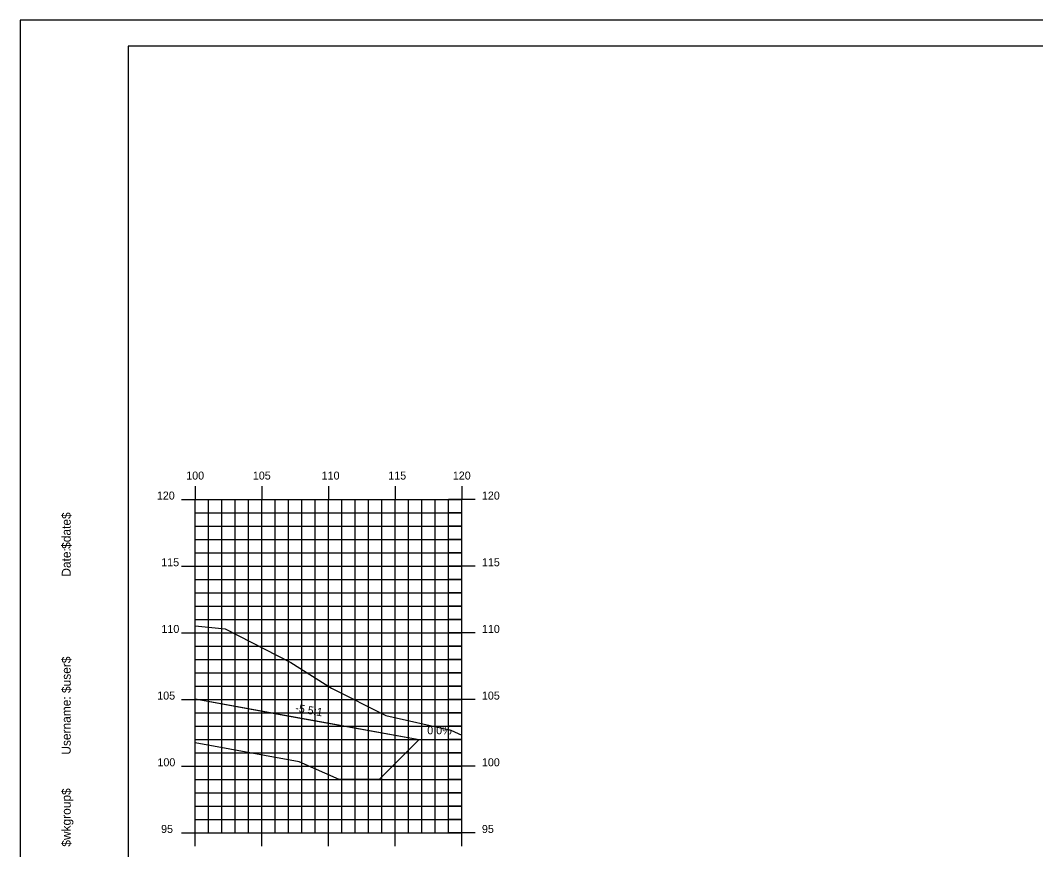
# Model space of a CAD drawing. Extents: x 850598 to 870284, y 366541 to 366651.
# Drawn here: x 858137.5 to 858213.6, y 366589 to 366651.2 of the extents above; entities that cross this region are included whole.
import ezdxf

# ---------------------------------------------------------------- set-up
doc = ezdxf.new("R2010")
doc.units = 0
for name, color, linetype in [('ANNOTATION', 7, 'Continuous'), ('BORDER', 7, 'Continuous'), ('D_Drainage_RipRap', 7, 'Continuous'), ('D_Roadway_Centerline', 7, 'Continuous'), ('D_Roadway_SlopeLines', 7, 'Continuous'), ('H_V ANNOTATION', 7, 'Continuous'), ('MAJOR', 7, 'Continuous'), ('MINOR', 7, 'Continuous'), ('PLOT BOUNDARY', 7, 'Continuous'), ('S_Roadway_Centerline', 7, 'Continuous')]:
    doc.layers.add(name, color=color, linetype=linetype)

msp = doc.modelspace()

# ---------------------------------------------------------------- linework, layer by layer
at = {"layer": 'BORDER'}
for p, q in [((858305.62, 366649.225), (858145.62, 366649.225)), ((858145.62, 366649.225), (858145.62, 366544.225))]:
    msp.add_line(p, q, dxfattribs=at)
at = {"layer": 'D_Drainage_RipRap'}
msp.add_lwpolyline([(858150.619, 366596.978), (858150.619, 366600.272), (858157.555, 366599.014), (858167.417, 366597.225), (858164.417, 366594.225), (858161.417, 366594.225), (858158.417, 366595.564)], close=True, dxfattribs=at)
at = {"layer": 'D_Roadway_Centerline'}
msp.add_lwpolyline([(858150.619, 366600.272), (858157.555, 366599.014), (858167.417, 366597.225), (858170.619, 366597.225)], dxfattribs=at)
at = {"layer": 'D_Roadway_SlopeLines'}
msp.add_lwpolyline([(858150.619, 366600.272), (858167.417, 366597.225)], dxfattribs=at)
at = {"layer": 'MAJOR'}
for p, q in [((858150.619, 366616.227), (858150.619, 366615.225)), ((858150.619, 366616.227), (858150.619, 366615.225)), ((858155.619, 366616.227), (858155.619, 366615.225)), ((858155.619, 366616.227), (858155.619, 366615.225)), ((858160.619, 366616.227), (858160.619, 366615.225)), ((858160.619, 366616.227), (858160.619, 366615.225)), ((858165.619, 366616.227), (858165.619, 366615.225)), ((858165.619, 366616.227), (858165.619, 366615.225)), ((858170.619, 366616.227), (858170.619, 366615.225)), ((858170.619, 366616.227), (858170.619, 366615.225)), ((858149.617, 366615.225), (858150.619, 366615.225)), ((858149.617, 366615.225), (858150.619, 366615.225)), ((858150.619, 366615.225), (858170.619, 366615.225)), ((858150.619, 366590.225), (858150.619, 366615.225)), ((858150.619, 366590.225), (858150.619, 366615.225)), ((858150.619, 366615.225), (858170.619, 366615.225)), ((858150.619, 366615.225), (858170.619, 366615.225)), ((858150.619, 366590.225), (858150.619, 366615.225)), ((858150.619, 366590.225), (858150.619, 366615.225)), ((858150.619, 366615.225), (858170.619, 366615.225)), ((858155.619, 366590.225), (858155.619, 366615.225)), ((858155.619, 366590.225), (858155.619, 366615.225)), ((858160.619, 366590.225), (858160.619, 366615.225)), ((858160.619, 366590.225), (858160.619, 366615.225)), ((858165.619, 366590.225), (858165.619, 366615.225)), ((858165.619, 366590.225), (858165.619, 366615.225)), ((858171.621, 366615.225), (858169.617, 366615.225)), ((858171.621, 366615.225), (858169.617, 366615.225)), ((858170.619, 366590.225), (858170.619, 366615.225)), ((858170.619, 366590.225), (858170.619, 366615.225)), ((858170.619, 366590.225), (858170.619, 366615.225)), ((858170.619, 366590.225), (858170.619, 366615.225)), ((858149.617, 366610.225), (858150.619, 366610.225)), ((858149.617, 366610.225), (858150.619, 366610.225)), ((858150.619, 366610.225), (858170.619, 366610.225)), ((858150.619, 366610.225), (858170.619, 366610.225)), ((858171.621, 366610.225), (858169.617, 366610.225)), ((858171.621, 366610.225), (858169.617, 366610.225)), ((858149.617, 366605.225), (858150.619, 366605.225)), ((858149.617, 366605.225), (858150.619, 366605.225)), ((858150.619, 366605.225), (858170.619, 366605.225)), ((858150.619, 366605.225), (858170.619, 366605.225)), ((858171.621, 366605.225), (858169.617, 366605.225)), ((858171.621, 366605.225), (858169.617, 366605.225)), ((858149.617, 366600.225), (858150.619, 366600.225)), ((858149.617, 366600.225), (858150.619, 366600.225)), ((858150.619, 366600.225), (858170.619, 366600.225)), ((858150.619, 366600.225), (858170.619, 366600.225)), ((858171.621, 366600.225), (858169.617, 366600.225)), ((858171.621, 366600.225), (858169.617, 366600.225)), ((858149.617, 366595.225), (858150.619, 366595.225)), ((858149.617, 366595.225), (858150.619, 366595.225)), ((858150.619, 366595.225), (858170.619, 366595.225)), ((858150.619, 366595.225), (858170.619, 366595.225)), ((858171.621, 366595.225), (858169.617, 366595.225)), ((858171.621, 366595.225), (858169.617, 366595.225)), ((858149.617, 366590.225), (858150.619, 366590.225)), ((858149.617, 366590.225), (858150.619, 366590.225)), ((858150.619, 366590.225), (858170.619, 366590.225)), ((858150.619, 366590.225), (858170.619, 366590.225)), ((858150.619, 366589.223), (858150.619, 366590.225)), ((858150.619, 366590.225), (858170.619, 366590.225)), ((858150.619, 366590.225), (858170.619, 366590.225)), ((858150.619, 366589.223), (858150.619, 366590.225)), ((858155.619, 366589.223), (858155.619, 366590.225)), ((858155.619, 366589.223), (858155.619, 366590.225)), ((858160.619, 366589.223), (858160.619, 366590.225)), ((858160.619, 366589.223), (858160.619, 366590.225)), ((858165.619, 366589.223), (858165.619, 366590.225)), ((858165.619, 366589.223), (858165.619, 366590.225)), ((858171.621, 366590.225), (858169.617, 366590.225)), ((858171.621, 366590.225), (858169.617, 366590.225)), ((858170.619, 366589.223), (858170.619, 366590.225)), ((858170.619, 366589.223), (858170.619, 366590.225))]:
    msp.add_line(p, q, dxfattribs=at)
at = {"layer": 'MINOR'}
for p, q in [((858151.619, 366590.225), (858151.619, 366615.225)), ((858151.619, 366590.225), (858151.619, 366615.225)), ((858152.619, 366590.225), (858152.619, 366615.225)), ((858152.619, 366590.225), (858152.619, 366615.225)), ((858153.619, 366590.225), (858153.619, 366615.225)), ((858153.619, 366590.225), (858153.619, 366615.225)), ((858154.619, 366590.225), (858154.619, 366615.225)), ((858154.619, 366590.225), (858154.619, 366615.225)), ((858156.619, 366590.225), (858156.619, 366615.225)), ((858156.619, 366590.225), (858156.619, 366615.225)), ((858157.619, 366590.225), (858157.619, 366615.225)), ((858157.619, 366590.225), (858157.619, 366615.225)), ((858158.619, 366590.225), (858158.619, 366615.225)), ((858158.619, 366590.225), (858158.619, 366615.225)), ((858159.619, 366590.225), (858159.619, 366615.225)), ((858159.619, 366590.225), (858159.619, 366615.225)), ((858161.619, 366590.225), (858161.619, 366615.225)), ((858161.619, 366590.225), (858161.619, 366615.225)), ((858162.619, 366590.225), (858162.619, 366615.225)), ((858162.619, 366590.225), (858162.619, 366615.225)), ((858163.619, 366590.225), (858163.619, 366615.225)), ((858163.619, 366590.225), (858163.619, 366615.225)), ((858164.619, 366590.225), (858164.619, 366615.225)), ((858164.619, 366590.225), (858164.619, 366615.225)), ((858166.619, 366590.225), (858166.619, 366615.225)), ((858166.619, 366590.225), (858166.619, 366615.225)), ((858167.619, 366590.225), (858167.619, 366615.225)), ((858167.619, 366590.225), (858167.619, 366615.225)), ((858168.619, 366590.225), (858168.619, 366615.225)), ((858168.619, 366590.225), (858168.619, 366615.225)), ((858169.619, 366590.225), (858169.619, 366615.225)), ((858169.619, 366590.225), (858169.619, 366615.225)), ((858150.619, 366614.225), (858170.619, 366614.225)), ((858150.619, 366614.225), (858151.621, 366614.225)), ((858150.619, 366614.225), (858170.619, 366614.225)), ((858150.619, 366614.225), (858151.621, 366614.225)), ((858170.619, 366614.225), (858169.617, 366614.225)), ((858170.619, 366614.225), (858169.617, 366614.225)), ((858150.619, 366613.225), (858170.619, 366613.225)), ((858150.619, 366613.225), (858151.621, 366613.225)), ((858150.619, 366613.225), (858170.619, 366613.225)), ((858150.619, 366613.225), (858151.621, 366613.225)), ((858170.619, 366613.225), (858169.617, 366613.225)), ((858170.619, 366613.225), (858169.617, 366613.225)), ((858150.619, 366612.225), (858170.619, 366612.225)), ((858150.619, 366612.225), (858151.621, 366612.225)), ((858150.619, 366612.225), (858170.619, 366612.225)), ((858150.619, 366612.225), (858151.621, 366612.225)), ((858170.619, 366612.225), (858169.617, 366612.225)), ((858170.619, 366612.225), (858169.617, 366612.225)), ((858150.619, 366611.225), (858170.619, 366611.225)), ((858150.619, 366611.225), (858151.621, 366611.225)), ((858150.619, 366611.225), (858170.619, 366611.225)), ((858150.619, 366611.225), (858151.621, 366611.225)), ((858170.619, 366611.225), (858169.617, 366611.225)), ((858170.619, 366611.225), (858169.617, 366611.225)), ((858150.619, 366609.225), (858170.619, 366609.225)), ((858150.619, 366609.225), (858151.621, 366609.225)), ((858150.619, 366609.225), (858170.619, 366609.225)), ((858150.619, 366609.225), (858151.621, 366609.225)), ((858170.619, 366609.225), (858169.617, 366609.225)), ((858170.619, 366609.225), (858169.617, 366609.225)), ((858150.619, 366608.225), (858170.619, 366608.225)), ((858150.619, 366608.225), (858151.621, 366608.225)), ((858150.619, 366608.225), (858170.619, 366608.225)), ((858150.619, 366608.225), (858151.621, 366608.225)), ((858170.619, 366608.225), (858169.617, 366608.225)), ((858170.619, 366608.225), (858169.617, 366608.225)), ((858150.619, 366607.225), (858170.619, 366607.225)), ((858150.619, 366607.225), (858151.621, 366607.225)), ((858150.619, 366607.225), (858170.619, 366607.225)), ((858150.619, 366607.225), (858151.621, 366607.225)), ((858170.619, 366607.225), (858169.617, 366607.225)), ((858170.619, 366607.225), (858169.617, 366607.225)), ((858150.619, 366606.225), (858170.619, 366606.225)), ((858150.619, 366606.225), (858151.621, 366606.225)), ((858150.619, 366606.225), (858170.619, 366606.225)), ((858150.619, 366606.225), (858151.621, 366606.225)), ((858170.619, 366606.225), (858169.617, 366606.225)), ((858170.619, 366606.225), (858169.617, 366606.225)), ((858150.619, 366604.225), (858170.619, 366604.225)), ((858150.619, 366604.225), (858151.621, 366604.225)), ((858150.619, 366604.225), (858170.619, 366604.225)), ((858150.619, 366604.225), (858151.621, 366604.225)), ((858170.619, 366604.225), (858169.617, 366604.225)), ((858170.619, 366604.225), (858169.617, 366604.225)), ((858150.619, 366603.225), (858170.619, 366603.225)), ((858150.619, 366603.225), (858151.621, 366603.225)), ((858150.619, 366603.225), (858170.619, 366603.225)), ((858150.619, 366603.225), (858151.621, 366603.225)), ((858170.619, 366603.225), (858169.617, 366603.225)), ((858170.619, 366603.225), (858169.617, 366603.225)), ((858150.619, 366602.225), (858170.619, 366602.225)), ((858150.619, 366602.225), (858151.621, 366602.225)), ((858150.619, 366602.225), (858170.619, 366602.225)), ((858150.619, 366602.225), (858151.621, 366602.225)), ((858170.619, 366602.225), (858169.617, 366602.225)), ((858170.619, 366602.225), (858169.617, 366602.225)), ((858150.619, 366601.225), (858170.619, 366601.225)), ((858150.619, 366601.225), (858151.621, 366601.225)), ((858150.619, 366601.225), (858170.619, 366601.225)), ((858150.619, 366601.225), (858151.621, 366601.225)), ((858170.619, 366601.225), (858169.617, 366601.225)), ((858170.619, 366601.225), (858169.617, 366601.225)), ((858150.619, 366599.225), (858170.619, 366599.225)), ((858150.619, 366599.225), (858151.621, 366599.225)), ((858150.619, 366599.225), (858170.619, 366599.225)), ((858150.619, 366599.225), (858151.621, 366599.225)), ((858170.619, 366599.225), (858169.617, 366599.225)), ((858170.619, 366599.225), (858169.617, 366599.225)), ((858150.619, 366598.225), (858170.619, 366598.225)), ((858150.619, 366598.225), (858151.621, 366598.225)), ((858150.619, 366598.225), (858170.619, 366598.225)), ((858150.619, 366598.225), (858151.621, 366598.225)), ((858170.619, 366598.225), (858169.617, 366598.225)), ((858170.619, 366598.225), (858169.617, 366598.225)), ((858150.619, 366597.225), (858170.619, 366597.225)), ((858150.619, 366597.225), (858151.621, 366597.225)), ((858150.619, 366597.225), (858170.619, 366597.225)), ((858150.619, 366597.225), (858151.621, 366597.225)), ((858170.619, 366597.225), (858169.617, 366597.225)), ((858170.619, 366597.225), (858169.617, 366597.225)), ((858150.619, 366596.225), (858170.619, 366596.225)), ((858150.619, 366596.225), (858151.621, 366596.225)), ((858150.619, 366596.225), (858170.619, 366596.225)), ((858150.619, 366596.225), (858151.621, 366596.225)), ((858170.619, 366596.225), (858169.617, 366596.225)), ((858170.619, 366596.225), (858169.617, 366596.225)), ((858150.619, 366594.225), (858170.619, 366594.225)), ((858150.619, 366594.225), (858151.621, 366594.225)), ((858150.619, 366594.225), (858170.619, 366594.225)), ((858150.619, 366594.225), (858151.621, 366594.225)), ((858170.619, 366594.225), (858169.617, 366594.225)), ((858170.619, 366594.225), (858169.617, 366594.225)), ((858150.619, 366593.225), (858170.619, 366593.225)), ((858150.619, 366593.225), (858151.621, 366593.225)), ((858150.619, 366593.225), (858170.619, 366593.225)), ((858150.619, 366593.225), (858151.621, 366593.225)), ((858170.619, 366593.225), (858169.617, 366593.225)), ((858170.619, 366593.225), (858169.617, 366593.225)), ((858150.619, 366592.225), (858170.619, 366592.225)), ((858150.619, 366592.225), (858151.621, 366592.225)), ((858150.619, 366592.225), (858170.619, 366592.225)), ((858150.619, 366592.225), (858151.621, 366592.225)), ((858170.619, 366592.225), (858169.617, 366592.225)), ((858170.619, 366592.225), (858169.617, 366592.225)), ((858150.619, 366591.225), (858170.619, 366591.225)), ((858150.619, 366591.225), (858151.621, 366591.225)), ((858150.619, 366591.225), (858170.619, 366591.225)), ((858150.619, 366591.225), (858151.621, 366591.225)), ((858170.619, 366591.225), (858169.617, 366591.225)), ((858170.619, 366591.225), (858169.617, 366591.225))]:
    msp.add_line(p, q, dxfattribs=at)
at = {"layer": 'PLOT BOUNDARY'}
msp.add_lwpolyline([(858137.526, 366541.166), (858307.526, 366541.166), (858307.526, 366651.166), (858137.526, 366651.166)], close=True, dxfattribs=at)
at = {"layer": 'S_Roadway_Centerline'}
msp.add_lwpolyline([(858150.619, 366605.747), (858152.876, 366605.538), (858157.799, 366603.014), (858160.841, 366601.095), (858164.922, 366599.041), (858169.798, 366597.923), (858170.619, 366597.569)], dxfattribs=at)

# ---------------------------------------------------------------- texts
at = {"layer": 'ANNOTATION'}
msp.add_text('-5.5:1', height=0.6, rotation=349.72041, dxfattribs=at).set_placement((858158.1, 366599.331))
msp.add_text('0.0%', height=0.6, dxfattribs=at).set_placement((858168.023, 366597.625))
at = {"layer": 'BORDER'}
for s, p in [('$date$', (858141.305, 366611.53)), ('Date:', (858141.305, 366609.442)), ('$user$', (858141.305, 366600.717)), ('Username:', (858141.305, 366596.093)), ('$wkgroup$', (858141.305, 366589.195))]:
    msp.add_text(s, height=0.6696, rotation=90, dxfattribs=at).set_placement(p)
at = {"layer": 'H_V ANNOTATION'}
for s, p in [('100', (858149.961, 366616.725)), ('105', (858154.953, 366616.725)), ('110', (858160.111, 366616.725)), ('115', (858165.103, 366616.725)), ('120', (858169.94, 366616.725)), ('120', (858147.76, 366615.225)), ('120', (858172.119, 366615.225)), ('115', (858148.087, 366610.225)), ('115', (858172.119, 366610.225)), ('110', (858148.103, 366605.225)), ('110', (858172.119, 366605.225)), ('105', (858147.787, 366600.225)), ('105', (858172.119, 366600.225)), ('100', (858147.803, 366595.225)), ('100', (858172.119, 366595.225)), ('95', (858148.076, 366590.225)), ('95', (858172.119, 366590.225))]:
    msp.add_text(s, height=0.6, dxfattribs=at).set_placement(p)

doc.saveas('drawing.dxf')
